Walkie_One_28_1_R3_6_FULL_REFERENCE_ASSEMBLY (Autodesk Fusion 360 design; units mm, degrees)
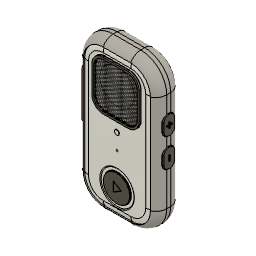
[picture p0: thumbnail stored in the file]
description: Open CASCADE Model
part number: Walkie_One_Concept_27_R2_REFERENCE_ASSEMBLY
description: Part Number
part number: C27_R2_04_Status_Lens
part number: C27_R2_05_Front_Switch_Clamp
part number: C27_R2_08_Volume_Down_Rigid_Carrier
part number: C27_R2_17_PTT_Bond_Film
part number: C27_R2_PCB_Front_Seat_1
part number: C27_R2_PCB_Front_Seat_2
part number: C27_R2_PCB_Rear_Preload_3
part number: C27_R2_PCB_Front_Seat_4
part number: C27_R2_Speaker_Front_Gasket
named bodies: "C28_R2_PCB_Front_Seat_2_Y10p2_REVIEW", "C28_R2_Microphone_BOTTOM_PORT_Offset_Seal_REVIEW", "C28_R2_PCB_Rear_Preload_2_Y10p2_REVIEW", "C28_R2_Microphone_Rear_Preload_Passive_Reliefs_REVIEW", "C28_R1_58_Grille_Perimeter_Bond_Film", "C28_R1_59_Mesh_Edge_Bond_Film", "C28_R1_60_Black_Acoustic_Scrim", "C28_R1_61_Graphite_Woven_Mesh_REFERENCE_RODS_001", "C28_R1_61_Graphite_Woven_Mesh_REFERENCE_RODS_002", "C28_R1_61_Graphite_Woven_Mesh_REFERENCE_RODS_003", "C28_R1_61_Graphite_Woven_Mesh_REFERENCE_RODS_004", "C28_R1_61_Graphite_Woven_Mesh_REFERENCE_RODS_005", "C28_R1_61_Graphite_Woven_Mesh_REFERENCE_RODS_006", "C28_R1_61_Graphite_Woven_Mesh_REFERENCE_RODS_007", "C28_R1_61_Graphite_Woven_Mesh_REFERENCE_RODS_008", "C28_R1_61_Graphite_Woven_Mesh_REFERENCE_RODS_009", "C28_R1_61_Graphite_Woven_Mesh_REFERENCE_RODS_010", "C28_R1_61_Graphite_Woven_Mesh_REFERENCE_RODS_011", "C28_R1_61_Graphite_Woven_Mesh_REFERENCE_RODS_012", "C28_R1_61_Graphite_Woven_Mesh_REFERENCE_RODS_013", "C28_R1_61_Graphite_Woven_Mesh_REFERENCE_RODS_014", "C28_R1_61_Graphite_Woven_Mesh_REFERENCE_RODS_015", "C28_R1_61_Graphite_Woven_Mesh_REFERENCE_RODS_016", "C28_R1_61_Graphite_Woven_Mesh_REFERENCE_RODS_017", "C28_R1_61_Graphite_Woven_Mesh_REFERENCE_RODS_018", "C28_R1_61_Graphite_Woven_Mesh_REFERENCE_RODS_019", "C28_R1_61_Graphite_Woven_Mesh_REFERENCE_RODS_020", "C28_R1_61_Graphite_Woven_Mesh_REFERENCE_RODS_021", "C28_R1_61_Graphite_Woven_Mesh_REFERENCE_RODS_022", "C28_R1_61_Graphite_Woven_Mesh_REFERENCE_RODS_023", "C28_R1_61_Graphite_Woven_Mesh_REFERENCE_RODS_024", "C28_R1_61_Graphite_Woven_Mesh_REFERENCE_RODS_025", "C28_R1_61_Graphite_Woven_Mesh_REFERENCE_RODS_026", "C28_R1_61_Graphite_Woven_Mesh_REFERENCE_RODS_027", "C28_R1_61_Graphite_Woven_Mesh_REFERENCE_RODS_028", "C28_R1_61_Graphite_Woven_Mesh_REFERENCE_RODS_029", "C28_R1_61_Graphite_Woven_Mesh_REFERENCE_RODS_030", "C28_R1_61_Graphite_Woven_Mesh_REFERENCE_RODS_031", "C28_R1_61_Graphite_Woven_Mesh_REFERENCE_RODS_032", "C28_R1_61_Graphite_Woven_Mesh_REFERENCE_RODS_033", "C28_R1_61_Graphite_Woven_Mesh_REFERENCE_RODS_034", "C28_R1_61_Graphite_Woven_Mesh_REFERENCE_RODS_035", "C28_R1_61_Graphite_Woven_Mesh_REFERENCE_RODS_036", "C28_R1_61_Graphite_Woven_Mesh_REFERENCE_RODS_037", "C28_R1_61_Graphite_Woven_Mesh_REFERENCE_RODS_038", "C28_R1_61_Graphite_Woven_Mesh_REFERENCE_RODS_039", "C28_R1_61_Graphite_Woven_Mesh_REFERENCE_RODS_040", "C28_R1_61_Graphite_Woven_Mesh_REFERENCE_RODS_041", "C28_R1_61_Graphite_Woven_Mesh_REFERENCE_RODS_042", "C28_R1_61_Graphite_Woven_Mesh_REFERENCE_RODS_043", "C28_R1_61_Graphite_Woven_Mesh_REFERENCE_RODS_044", "C28_R1_61_Graphite_Woven_Mesh_REFERENCE_RODS_045", "C28_R1_61_Graphite_Woven_Mesh_REFERENCE_RODS_046", "C28_R1_61_Graphite_Woven_Mesh_REFERENCE_RODS_047", "C28_R1_61_Graphite_Woven_Mesh_REFERENCE_RODS_048", "C28_R1_61_Graphite_Woven_Mesh_REFERENCE_RODS_049", "C28_R1_61_Graphite_Woven_Mesh_REFERENCE_RODS_050", "C28_R1_61_Graphite_Woven_Mesh_REFERENCE_RODS_051", "C28_R1_61_Graphite_Woven_Mesh_REFERENCE_RODS_052", "C28_R1_61_Graphite_Woven_Mesh_REFERENCE_RODS_053"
